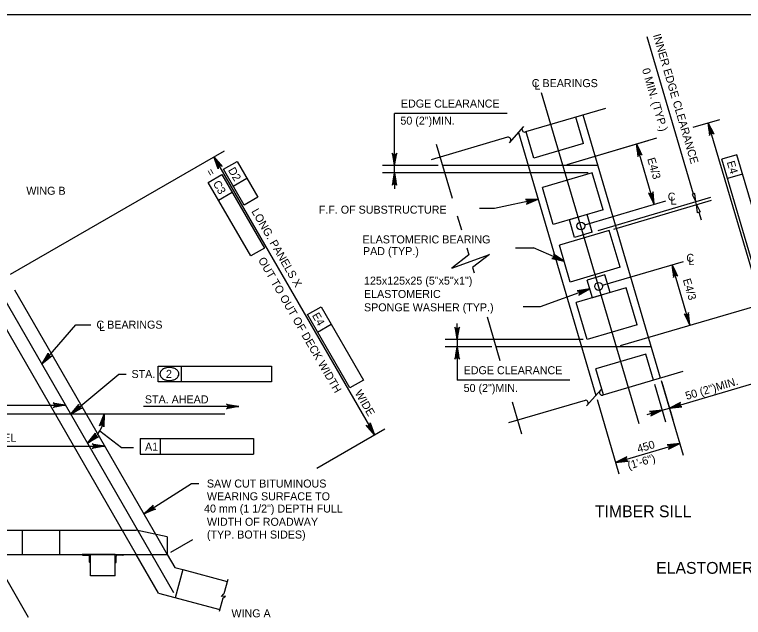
# Model space of a CAD drawing. Extents: x 638268 to 640277, y 295465 to 298435.
# Drawn here: x 639628.9 to 639902.1, y 297006.4 to 297232.5 of the extents above; entities that cross this region are included whole.
import ezdxf

# ---------------------------------------------------------------- set-up
doc = ezdxf.new("R2010")
doc.units = 0
for name, color, linetype in [('2', 7, 'Continuous'), ('3', 7, 'Continuous'), ('4', 7, 'Continuous'), ('7', 7, 'Continuous')]:
    doc.layers.add(name, color=color, linetype=linetype)

msp = doc.modelspace()

# ---------------------------------------------------------------- linework, layer by layer
at = {"layer": '2'}
for p, q in [((639316.46, 297232.46), (640102.46, 297232.46)), ((639614.31, 297134.29), (639674.49, 297030.06)), ((639628.88, 297129.24), (639682.63, 297036.13)), ((639539.28, 297039.18), (639674.46, 297039.18)), ((639631.81, 297030.06), (639631.81, 297039.18)), ((639645.83, 297030.06), (639645.83, 297039.18)), ((639686.14, 297036.58), (639674.46, 297039.18)), ((639686.14, 297036.58), (639686.14, 297030.06)), ((639682.63, 297036.13), (639686.14, 297030.06)), ((639492.13, 297030.06), (639686.14, 297030.06)), ((639492.13, 297030.06), (639686.14, 297030.06)), ((639654.29, 297029.88), (639654.29, 297030.06)), ((639657.38, 297030.06), (639654.29, 297030.06)), ((639654.48, 297029.7), (639656.66, 297029.7)), ((639657.02, 297027.15), (639657.02, 297029.33)), ((639666.62, 297030.06), (639657.38, 297030.06)), ((639657.38, 297026.97), (639657.38, 297030.06)), ((639657.38, 297021.97), (639657.38, 297030.06)), ((639666.62, 297026.97), (639666.62, 297030.06)), ((639666.62, 297030.06), (639669.71, 297030.06)), ((639666.62, 297021.97), (639666.62, 297030.06)), ((639666.98, 297027.15), (639666.98, 297029.33)), ((639669.53, 297029.7), (639667.35, 297029.7)), ((639669.71, 297029.88), (639669.71, 297030.06)), ((639682.91, 297015.46), (639674.49, 297030.06)), ((639686.14, 297030.06), (639688.98, 297025.13)), ((639657.2, 297026.97), (639657.38, 297026.97)), ((639666.8, 297026.97), (639666.62, 297026.97)), ((639688.98, 297025.13), (639691.94, 297024.34)), ((639691.94, 297024.34), (639689.11, 297013.8)), ((639691.94, 297024.34), (639708.62, 297019.87)), ((639666.62, 297021.97), (639657.38, 297021.97)), ((639682.91, 297015.46), (639705.79, 297009.33))]:
    msp.add_line(p, q, dxfattribs=at)
for centre, radius, start, end in [((639654.48, 297029.88), 0.182, 180.0016, 270), ((639656.66, 297029.33), 0.364, 0.0016, 90), ((639667.35, 297029.33), 0.364, 90, 179.9984), ((639669.53, 297029.88), 0.182, 270, 359.9984), ((639657.2, 297027.15), 0.182, 180.0016, 270), ((639666.8, 297027.15), 0.182, 270, 359.9984)]:
    msp.add_arc(centre, radius, start, end, dxfattribs=at)
at = {"layer": '3'}
for p, q in [((639850.43, 297197.27), (639820.41, 297188.43)), ((639871.06, 297096.14), (639842.01, 297194.79)), ((639883.33, 297190.23), (639893.29, 297193.16)), ((639819.72, 297190.5), (639814.31, 297184.36)), ((639908.99, 297123.91), (639888.97, 297191.89)), ((639813.71, 297186.46), (639785.03, 297178.01)), ((639817.76, 297188.28), (639846.82, 297089.63)), ((639786.97, 297183.81), (639792.9, 297163.67)), ((639842.23, 297184.11), (639823.54, 297178.6)), ((639836.01, 297176.29), (639869.64, 297186.19)), ((639847.59, 297175.85), (639789.32, 297175.85)), ((639845.48, 297173.09), (639826.78, 297167.59)), ((639847.72, 297151.52), (639889.91, 297163.95)), ((639853.53, 297152.03), (639890.23, 297162.85)), ((639849.55, 297159.25), (639830.86, 297153.74)), ((639794.88, 297156.95), (639796.43, 297151.7)), ((639843.51, 297157.46), (639836.9, 297155.52)), ((639851.83, 297151.53), (639833.13, 297146.03)), ((639845.46, 297150.86), (639838.85, 297148.91)), ((639798.4, 297145.01), (639799.17, 297142.38)), ((639800.59, 297137.59), (639801.16, 297135.65)), ((639855.9, 297137.69), (639837.21, 297132.18)), ((639850.19, 297134.81), (639843.58, 297132.86)), ((639858.18, 297129.98), (639839.48, 297124.47)), ((639852.13, 297128.2), (639845.53, 297126.25)), ((639856.03, 297108.31), (639913.31, 297125.18)), ((639806.04, 297119.06), (639810.85, 297102.76)), ((639862.25, 297116.13), (639843.56, 297110.62)), ((639867.61, 297107.87), (639809.34, 297107.87)), ((639865.5, 297105.11), (639846.81, 297099.61)), ((639879.48, 297098.62), (639849.47, 297089.78)), ((639848.78, 297091.85), (639843.36, 297085.71)), ((639842.76, 297087.81), (639814.08, 297079.36)), ((639815.4, 297087.29), (639818.93, 297075.3)), ((639708.84, 297020.69), (639707.37, 297015.22)), ((639706.5, 297014.27), (639707.37, 297015.22)), ((639707.96, 297014.36), (639706.5, 297014.27)), ((639706.93, 297013.59), (639707.96, 297014.36)), ((639706.93, 297013.59), (639705.59, 297008.59))]:
    msp.add_line(p, q, dxfattribs=at)
msp.add_lwpolyline([(639890.3, 297189.15), (639889.34, 297188.87), (639888.97, 297191.89)], close=True, dxfattribs=at)
for centre, start, end in [((639820.13, 297189.41), 136.412, 286.412), ((639813.9, 297185.45), 318.5448, 101.0834), ((639849.18, 297090.76), 136.412, 286.412), ((639842.96, 297086.8), 318.5448, 101.0834)]:
    msp.add_arc(centre, 1.02, start, end, dxfattribs=at)
at = {"layer": '4'}
for p, q in [((639883.43, 297165.17), (639866.06, 297224.16)), ((639863.01, 297079.06), (639826.47, 297203.14)), ((639771.31, 297178.85), (639771.31, 297195.39)), ((639813.58, 297195.39), (639771.31, 297195.39)), ((639688.63, 297015.66), (639589.95, 297186.58)), ((639836.01, 297176.29), (639866.38, 297185.23)), ((639868.74, 297161.3), (639862.06, 297183.96)), ((639627.32, 297135.07), (639707.53, 297181.38)), ((639703.63, 297179.13), (639763.8, 297074.9)), ((639899.69, 297179.91), (639894.03, 297178.24)), ((639906.04, 297137.45), (639894.03, 297178.24)), ((639911.7, 297139.12), (639899.69, 297179.91)), ((639707.2, 297174.46), (639712.32, 297177.42)), ((639712.32, 297177.42), (639720.06, 297164)), ((639787.75, 297175.85), (639766.81, 297175.85)), ((639771.31, 297173.09), (639771.31, 297175.85)), ((639714.95, 297161.05), (639707.2, 297174.46)), ((639843.91, 297173.09), (639766.81, 297173.09)), ((639701.52, 297169.49), (639706.64, 297172.44)), ((639706.64, 297172.44), (639722.53, 297144.92)), ((639710.84, 297168.16), (639715.96, 297171.11)), ((639771.31, 297170.09), (639771.31, 297167.09)), ((639901.83, 297172.65), (639896.16, 297170.99)), ((639717.41, 297141.97), (639701.52, 297169.49)), ((639705.35, 297162.87), (639710.46, 297165.82)), ((639720.06, 297164), (639714.95, 297161.05)), ((639842.68, 297153.63), (639873.05, 297162.57)), ((639884.6, 297161.19), (639884.28, 297162.29)), ((639808.76, 297159.78), (639803.23, 297159.78)), ((639885.45, 297158.31), (639886.3, 297155.43)), ((639722.53, 297144.92), (639717.41, 297141.97)), ((639823.57, 297144.87), (639816.72, 297144.87)), ((639849.35, 297130.97), (639879.73, 297139.91)), ((639882.08, 297115.98), (639875.41, 297138.64)), ((639738.67, 297119.98), (639743.78, 297122.93)), ((639743.78, 297122.93), (639759.67, 297095.41)), ((639825.95, 297122.92), (639819.57, 297122.92)), ((639754.56, 297092.46), (639738.67, 297119.98)), ((639639.12, 297101.41), (639651.85, 297116.15)), ((639651.85, 297116.15), (639657.47, 297116.15)), ((639742.49, 297113.35), (639747.61, 297116.31)), ((639794.84, 297113.62), (639794.84, 297116.62)), ((639856.03, 297108.31), (639886.4, 297117.26)), ((639842, 297110.62), (639790.34, 297110.62)), ((639794.84, 297110.62), (639794.84, 297107.87)), ((639807.78, 297107.87), (639790.34, 297107.87)), ((639794.84, 297104.87), (639794.84, 297095.4)), ((639682.7, 297094.75), (639682.7, 297100.65)), ((639682.7, 297100.65), (639725.22, 297100.65)), ((639691.45, 297094.75), (639691.45, 297100.65)), ((639725.22, 297100.65), (639725.22, 297094.75)), ((639649.99, 297082.58), (639667.92, 297097.57)), ((639667.92, 297097.57), (639670.69, 297097.57)), ((639874.38, 297084.88), (639914.06, 297096.57)), ((639725.22, 297094.75), (639682.7, 297094.75)), ((639759.67, 297095.41), (639754.56, 297092.46)), ((639837.1, 297095.4), (639794.84, 297095.4)), ((639868.82, 297093.85), (639872.96, 297079.78)), ((639871.34, 297095.22), (639879.57, 297067.28)), ((639871.51, 297094.65), (639875.65, 297080.57)), ((639847.26, 297088.13), (639855.49, 297060.19)), ((639468.6, 297085.95), (639648.04, 297085.95)), ((639713.02, 297085.52), (639677.21, 297085.52)), ((639871.69, 297084.09), (639865.94, 297082.4)), ((639871.69, 297084.09), (639874.38, 297084.89)), ((639707.69, 297082.58), (639405.47, 297082.58)), ((639742.18, 297062.42), (639767.7, 297077.15)), ((639660.83, 297076.32), (639669.01, 297070.11)), ((639675.94, 297073.48), (639718.45, 297073.48)), ((639675.94, 297073.48), (639675.94, 297067.58)), ((639683.5, 297073.48), (639683.5, 297067.58)), ((639718.45, 297073.48), (639718.45, 297067.58)), ((639471.61, 297070.65), (639662.7, 297070.65)), ((639669.01, 297070.11), (639673.48, 297070.11)), ((639854.22, 297064.5), (639878.3, 297071.6)), ((639598.34, 297068.34), (639634.03, 297006.52)), ((639675.94, 297067.58), (639718.45, 297067.58)), ((639677.37, 297045.24), (639695.2, 297056.69)), ((639695.2, 297056.69), (639697.97, 297056.69)), ((639687.49, 297030.84), (639695.73, 297035.6))]:
    msp.add_line(p, q, dxfattribs=at)
for points in [[(639888.97, 297191.89), (639889.45, 297187.17), (639889.59, 297187.59), (639889.83, 297187.85), (639890.12, 297187.99), (639890.43, 297188.03), (639890.78, 297187.94), (639891.12, 297187.67), (639888.97, 297191.89), (639890.78, 297187.94), (639890.43, 297188.03), (639888.97, 297191.89), (639890.12, 297187.99), (639889.83, 297187.85), (639888.97, 297191.89), (639889.59, 297187.59)], [(639862.06, 297183.96), (639862.54, 297179.25), (639862.68, 297179.66), (639862.92, 297179.92), (639863.21, 297180.06), (639863.52, 297180.1), (639863.88, 297180.01), (639864.21, 297179.74), (639862.06, 297183.96), (639863.88, 297180.01), (639863.52, 297180.1), (639862.06, 297183.96), (639863.21, 297180.06), (639862.92, 297179.92), (639862.06, 297183.96), (639862.68, 297179.66)], [(639703.63, 297179.13), (639706.72, 297175.53), (639706.32, 297175.71), (639705.96, 297175.72), (639705.66, 297175.61), (639705.42, 297175.41), (639705.24, 297175.09), (639705.2, 297174.65), (639703.63, 297179.13), (639705.24, 297175.09), (639705.42, 297175.41), (639703.63, 297179.13), (639705.66, 297175.61), (639705.96, 297175.72), (639703.63, 297179.13), (639706.32, 297175.71)], [(639771.31, 297175.85), (639772.19, 297180.51), (639771.94, 297180.15), (639771.63, 297179.96), (639771.31, 297179.91), (639771, 297179.96), (639770.69, 297180.15), (639770.44, 297180.51), (639771.31, 297175.85), (639770.69, 297180.15), (639771, 297179.96), (639771.31, 297175.85), (639771.31, 297179.91), (639771.63, 297179.96), (639771.31, 297175.85), (639771.94, 297180.15)], [(639771.31, 297173.09), (639770.44, 297168.43), (639770.69, 297168.79), (639771, 297168.97), (639771.31, 297169.03), (639771.63, 297168.97), (639771.94, 297168.79), (639772.19, 297168.43), (639771.31, 297173.09), (639771.94, 297168.79), (639771.63, 297168.97), (639771.31, 297173.09), (639771.31, 297169.03), (639771, 297168.97), (639771.31, 297173.09), (639770.69, 297168.79)], [(639868.74, 297161.3), (639868.26, 297166.02), (639868.12, 297165.61), (639867.87, 297165.34), (639867.59, 297165.2), (639867.27, 297165.16), (639866.92, 297165.25), (639866.58, 297165.53), (639868.74, 297161.3), (639866.92, 297165.25), (639867.27, 297165.16), (639868.74, 297161.3), (639867.59, 297165.2), (639867.87, 297165.34), (639868.74, 297161.3), (639868.12, 297165.61)], [(639825.14, 297163.23), (639808.76, 297159.78)], [(639825.14, 297163.23), (639820.4, 297163.12), (639820.8, 297162.96), (639821.05, 297162.69), (639821.17, 297162.39), (639821.18, 297162.08), (639821.06, 297161.73), (639820.76, 297161.42), (639825.14, 297163.23), (639821.06, 297161.73), (639821.18, 297162.08), (639825.14, 297163.23), (639821.17, 297162.39), (639821.05, 297162.69), (639825.14, 297163.23), (639820.8, 297162.96)], [(639834.91, 297139.97), (639823.41, 297144.94)], [(639799.17, 297142.38), (639792.84, 297137.35), (639806.97, 297142.45), (639800.58, 297137.59)], [(639834.91, 297139.97), (639830.98, 297142.62), (639831.21, 297142.25), (639831.26, 297141.89), (639831.19, 297141.58), (639831.01, 297141.32), (639830.72, 297141.11), (639830.29, 297141.02), (639834.91, 297139.97), (639830.72, 297141.11), (639831.01, 297141.32), (639834.91, 297139.97), (639831.19, 297141.58), (639831.26, 297141.89), (639834.91, 297139.97), (639831.21, 297142.25)], [(639875.41, 297138.64), (639875.89, 297133.93), (639876.03, 297134.34), (639876.27, 297134.61), (639876.56, 297134.75), (639876.87, 297134.78), (639877.22, 297134.69), (639877.56, 297134.42), (639875.41, 297138.64), (639877.22, 297134.69), (639876.87, 297134.78), (639875.41, 297138.64), (639876.56, 297134.75), (639876.27, 297134.61), (639875.41, 297138.64), (639876.03, 297134.34)], [(639844.54, 297129.61), (639825.94, 297122.92)], [(639844.54, 297129.61), (639839.85, 297128.85), (639840.28, 297128.74), (639840.56, 297128.51), (639840.71, 297128.23), (639840.77, 297127.92), (639840.7, 297127.56), (639840.45, 297127.21), (639844.54, 297129.61), (639840.7, 297127.56), (639840.77, 297127.92), (639844.54, 297129.61), (639840.71, 297128.23), (639840.56, 297128.51), (639844.54, 297129.61), (639840.28, 297128.74)], [(639882.08, 297115.98), (639881.6, 297120.7), (639881.47, 297120.29), (639881.22, 297120.02), (639880.94, 297119.88), (639880.62, 297119.85), (639880.27, 297119.93), (639879.93, 297120.21), (639882.08, 297115.98), (639880.27, 297119.93), (639880.62, 297119.85), (639882.08, 297115.98), (639880.94, 297119.88), (639881.22, 297120.02), (639882.08, 297115.98), (639881.47, 297120.29)], [(639794.84, 297110.62), (639795.71, 297115.28), (639795.46, 297114.93), (639795.15, 297114.74), (639794.84, 297114.69), (639794.52, 297114.74), (639794.21, 297114.93), (639793.96, 297115.28), (639794.84, 297110.62), (639794.21, 297114.93), (639794.52, 297114.74), (639794.84, 297110.62), (639794.84, 297114.69), (639795.15, 297114.74), (639794.84, 297110.62), (639795.46, 297114.93)], [(639794.84, 297107.87), (639793.96, 297103.21), (639794.21, 297103.57), (639794.52, 297103.75), (639794.84, 297103.81), (639795.15, 297103.75), (639795.46, 297103.57), (639795.71, 297103.21), (639794.84, 297107.87), (639795.46, 297103.57), (639795.15, 297103.75), (639794.84, 297107.87), (639794.84, 297103.81), (639794.52, 297103.75), (639794.84, 297107.87), (639794.21, 297103.57)], [(639639.12, 297101.41), (639641.5, 297105.51), (639641.46, 297105.07), (639641.57, 297104.73), (639641.77, 297104.48), (639642.05, 297104.32), (639642.4, 297104.26), (639642.83, 297104.36), (639639.12, 297101.41), (639642.4, 297104.26), (639642.05, 297104.32), (639639.12, 297101.41), (639641.77, 297104.48), (639641.57, 297104.73), (639639.12, 297101.41), (639641.46, 297105.07)], [(639648.04, 297085.95), (639643.38, 297085.08), (639643.74, 297085.33), (639643.93, 297085.64), (639643.98, 297085.95), (639643.93, 297086.27), (639643.74, 297086.58), (639643.38, 297086.83), (639648.04, 297085.95), (639643.74, 297086.58), (639643.93, 297086.27), (639648.04, 297085.95), (639643.98, 297085.95), (639643.93, 297085.64), (639648.04, 297085.95), (639643.74, 297085.33)], [(639649.99, 297082.58), (639653, 297086.24), (639652.89, 297085.82), (639652.95, 297085.46), (639653.11, 297085.19), (639653.35, 297084.98), (639653.69, 297084.86), (639654.12, 297084.9), (639649.99, 297082.58), (639653.69, 297084.86), (639653.35, 297084.98), (639649.99, 297082.58), (639653.11, 297085.19), (639652.95, 297085.46), (639649.99, 297082.58), (639652.89, 297085.82)], [(639713.02, 297085.52), (639708.36, 297084.65), (639708.72, 297084.89), (639708.91, 297085.21), (639708.96, 297085.52), (639708.91, 297085.83), (639708.72, 297086.14), (639708.36, 297086.39), (639713.02, 297085.52), (639708.72, 297086.14), (639708.91, 297085.83), (639713.02, 297085.52), (639708.96, 297085.52), (639708.91, 297085.21), (639713.02, 297085.52), (639708.72, 297084.89)], [(639874.38, 297084.88), (639879.1, 297085.36), (639878.68, 297085.5), (639878.42, 297085.75), (639878.28, 297086.03), (639878.24, 297086.35), (639878.33, 297086.7), (639878.6, 297087.04), (639874.38, 297084.88), (639878.33, 297086.7), (639878.24, 297086.35), (639874.38, 297084.88), (639878.28, 297086.03), (639878.42, 297085.75), (639874.38, 297084.88), (639878.68, 297085.5)], [(639871.69, 297084.09), (639866.98, 297083.61), (639867.39, 297083.48), (639867.65, 297083.23), (639867.79, 297082.95), (639867.83, 297082.63), (639867.74, 297082.28), (639867.47, 297081.94), (639871.69, 297084.09), (639867.74, 297082.28), (639867.83, 297082.63), (639871.69, 297084.09), (639867.79, 297082.95), (639867.65, 297083.23), (639871.69, 297084.09), (639867.39, 297083.48)], [(639662.51, 297082.58), (639662.4, 297077.84), (639662.23, 297078.24), (639661.96, 297078.49), (639661.67, 297078.61), (639661.35, 297078.62), (639661.01, 297078.5), (639660.69, 297078.2), (639662.51, 297082.58), (639661.01, 297078.5), (639661.35, 297078.62), (639662.51, 297082.58), (639661.67, 297078.61), (639661.96, 297078.49), (639662.51, 297082.58), (639662.23, 297078.24)], [(639763.8, 297074.9), (639760.72, 297078.5), (639761.11, 297078.31), (639761.48, 297078.31), (639761.77, 297078.42), (639762.02, 297078.62), (639762.2, 297078.94), (639762.23, 297079.37), (639763.8, 297074.9), (639762.2, 297078.94), (639762.02, 297078.62), (639763.8, 297074.9), (639761.77, 297078.42), (639761.48, 297078.31), (639763.8, 297074.9), (639761.11, 297078.31)], [(639656.25, 297071.74), (639659.2, 297075.45), (639659.1, 297075.03), (639659.16, 297074.67), (639659.32, 297074.4), (639659.57, 297074.19), (639659.91, 297074.08), (639660.35, 297074.13), (639656.25, 297071.74), (639659.91, 297074.08), (639659.57, 297074.19), (639656.25, 297071.74), (639659.32, 297074.4), (639659.16, 297074.67), (639656.25, 297071.74), (639659.1, 297075.03)], [(639662.7, 297070.65), (639658.04, 297069.78), (639658.4, 297070.03), (639658.59, 297070.34), (639658.64, 297070.65), (639658.59, 297070.96), (639658.4, 297071.28), (639658.04, 297071.52), (639662.7, 297070.65), (639658.4, 297071.28), (639658.59, 297070.96), (639662.7, 297070.65), (639658.64, 297070.65), (639658.59, 297070.34), (639662.7, 297070.65), (639658.4, 297070.03)], [(639878.3, 297071.6), (639873.58, 297071.12), (639873.99, 297070.98), (639874.26, 297070.73), (639874.4, 297070.45), (639874.44, 297070.13), (639874.35, 297069.78), (639874.07, 297069.44), (639878.3, 297071.6), (639874.35, 297069.78), (639874.44, 297070.13), (639878.3, 297071.6), (639874.4, 297070.45), (639874.26, 297070.73), (639878.3, 297071.6), (639873.99, 297070.98)], [(639854.22, 297064.5), (639858.94, 297064.98), (639858.52, 297065.12), (639858.26, 297065.37), (639858.12, 297065.65), (639858.08, 297065.97), (639858.17, 297066.32), (639858.44, 297066.66), (639854.22, 297064.5), (639858.17, 297066.32), (639858.08, 297065.97), (639854.22, 297064.5), (639858.12, 297065.65), (639858.26, 297065.37), (639854.22, 297064.5), (639858.52, 297065.12)], [(639677.37, 297045.24), (639680.82, 297048.49), (639680.66, 297048.09), (639680.67, 297047.73), (639680.79, 297047.43), (639681.01, 297047.2), (639681.33, 297047.04), (639681.77, 297047.02), (639677.37, 297045.24), (639681.33, 297047.04), (639681.01, 297047.2), (639677.37, 297045.24), (639680.79, 297047.43), (639680.67, 297047.73), (639677.37, 297045.24), (639680.66, 297048.09)]]:
    msp.add_lwpolyline(points, dxfattribs=at)
for points in [[(639863.39, 297181.23), (639862.43, 297180.94), (639862.06, 297183.96)], [(639705.56, 297176.78), (639704.7, 297176.28), (639703.63, 297179.13)], [(639771.81, 297178.85), (639770.81, 297178.85), (639771.31, 297175.85)], [(639771.81, 297170.09), (639770.81, 297170.09), (639771.31, 297173.09)], [(639883.91, 297165.31), (639882.95, 297165.03), (639884.28, 297162.29)], [(639825.14, 297163.23), (639822.26, 297162.37), (639822.15, 297162.86)], [(639868.37, 297164.32), (639867.41, 297164.04), (639868.74, 297161.3)], [(639885.93, 297158.45), (639884.97, 297158.17), (639884.6, 297161.19)], [(639834.91, 297139.97), (639832.06, 297140.93), (639832.26, 297141.39)], [(639876.74, 297135.91), (639875.78, 297135.62), (639875.41, 297138.64)], [(639844.54, 297129.61), (639841.8, 297128.36), (639841.63, 297128.83)], [(639881.71, 297119), (639880.76, 297118.72), (639882.08, 297115.98)], [(639795.34, 297113.62), (639794.34, 297113.62), (639794.84, 297110.62)], [(639795.34, 297104.87), (639794.34, 297104.87), (639794.84, 297107.87)], [(639877.12, 297086.21), (639877.4, 297085.25), (639874.38, 297084.89)], [(639651.82, 297084.71), (639652.41, 297084), (639649.99, 297082.58)], [(639868.67, 297083.73), (639868.95, 297082.77), (639871.69, 297084.09)], [(639762.74, 297077.75), (639761.87, 297077.25), (639763.8, 297074.9)], [(639875.28, 297071.23), (639875.56, 297070.27), (639878.3, 297071.6)], [(639856.96, 297065.83), (639857.24, 297064.87), (639854.22, 297064.5)], [(639680.32, 297046.58), (639679.82, 297047.36), (639677.74, 297045.47)]]:
    msp.add_lwpolyline(points, close=True, dxfattribs=at)
for centre, radius, start, end in [((639685.95, 297097.13), 2.75, 124.109, 148.5507), ((639686.55, 297096.24), 3.82, 105.6708, 124.109), ((639686.94, 297094.84), 5.27, 90, 105.6708), ((639686.94, 297094.84), 5.27, 74.3292, 90), ((639687.33, 297096.24), 3.82, 55.891, 74.3292), ((639687.93, 297097.13), 2.75, 31.4493, 55.891), ((639685.03, 297097.69), 1.68, 148.5507, 180), ((639685.03, 297097.69), 1.68, 180, 211.4493), ((639685.95, 297098.25), 2.75, 211.4493, 235.891), ((639687.93, 297098.25), 2.75, 304.109, 328.5507), ((639688.84, 297097.69), 1.68, 0, 31.4493), ((639688.84, 297097.69), 1.68, 328.5507, 0), ((639686.55, 297099.13), 3.82, 235.891, 254.3292), ((639686.94, 297100.53), 5.27, 254.3292, 270), ((639686.94, 297100.53), 5.27, 270, 285.6708), ((639687.33, 297099.13), 3.82, 285.6708, 304.109), ((639649.99, 297082.58), 12.52, 299.9992, 0.0004)]:
    msp.add_arc(centre, radius, start, end, dxfattribs=at)
at = {"layer": '7'}
for p, q in [((639842.23, 297184.11), (639839.32, 297194)), ((639823.54, 297178.6), (639820.63, 297188.49)), ((639849.55, 297159.25), (639845.48, 297173.09)), ((639830.86, 297153.74), (639826.78, 297167.59)), ((639845.46, 297150.86), (639843.51, 297157.46)), ((639838.85, 297148.91), (639836.9, 297155.52)), ((639855.9, 297137.69), (639851.83, 297151.53)), ((639837.21, 297132.18), (639833.13, 297146.03)), ((639852.13, 297128.2), (639850.19, 297134.81)), ((639845.53, 297126.25), (639843.58, 297132.86)), ((639862.25, 297116.13), (639858.18, 297129.98)), ((639843.56, 297110.62), (639839.48, 297124.47)), ((639868.38, 297095.35), (639865.5, 297105.11)), ((639849.68, 297089.85), (639846.81, 297099.61))]:
    msp.add_line(p, q, dxfattribs=at)
for centre in [(639841.18, 297153.19), (639847.86, 297130.53)]:
    msp.add_circle(centre, 1.48, dxfattribs=at)

# ---------------------------------------------------------------- texts
at = {"layer": '3'}
for s, p in [('TIMBER SILL', (639846.46, 297043.99)), ('ELASTOMERIC BEARING PAD ARRANGEMENTS', (639869.42, 297022.77))]:
    msp.add_text(s, height=4.4292, dxfattribs=at).set_placement(p)
at = {"layer": '4'}
for s, rotation, p in [('INNER EDGE CLEARANCE', 286.412, (639868.21, 297224.73)), ('0 MIN. (TYP.)', 286.412, (639864.06, 297211.89)), ('E4/3', 286.412, (639866.04, 297178.35)), ('E4', 286.4738, (639895.87, 297177.12)), ('=', 300, (639700.55, 297173.65)), ('D2', 300, (639708.82, 297174.14)), ('C3', 300, (639703.14, 297169.17)), ('LONG. PANELS X', 300, (639717.58, 297158.67)), ('OUT TO OUT OF DECK WIDTH', 300, (639720.08, 297140.43)), ('E4/3', 286.412, (639879.39, 297133.03)), ('E4', 300, (639740.29, 297119.65)), ('50 (2")MIN.', 16.4163, (639880.88, 297087.95)), ('WIDE', 300, (639756.32, 297090.62)), ('A1', 359.9382, (639677.8, 297068.93)), ('450', 16.4163, (639862.78, 297068.11)), ('(1\'-6")', 16.4163, (639859.19, 297061.84))]:
    msp.add_text(s, height=3, rotation=rotation, dxfattribs=at).set_placement(p)
for s, p in [('C BEARINGS', (639822.8, 297205.25)), ('L', (639823.82, 297204.34)), ('EDGE CLEARANCE', (639773.73, 297197.59)), ('50 (2")MIN.', (639773.54, 297191.18)), ('WING B', (639633.29, 297164.9)), ('C', (639873.77, 297162.69)), ('L', (639874.83, 297161.17)), ('F.F. OF SUBSTRUCTURE', (639742.94, 297157.81)), ('ELASTOMERIC BEARING', (639759.36, 297146.65)), ('PAD (TYP.)', (639759.51, 297142.27)), ('C', (639880.75, 297139.73)), ('L', (639881.5, 297138.51)), ('125x125x25 (5"x5"x1")', (639759.89, 297131.19)), ('ELASTOMERIC', (639759.89, 297126.19)), ('SPONGE WASHER (TYP.)', (639759.89, 297121.19)), ('C BEARINGS', (639659.6, 297114.69)), ('L', (639660.55, 297113.83)), ('STA.', (639672.74, 297096.18)), ('2', (639685.64, 297096.23)), ('EDGE CLEARANCE', (639797.25, 297097.6)), ('50 (2")MIN.', (639797.25, 297090.95)), ('STA. AHEAD', (639677.75, 297086.67)), ('OUT TO OUT LONGITUDINAL PANEL', (639559.76, 297072.27)), ('SAW CUT BITUMINOUS', (639701, 297055.11)), ('WEARING SURFACE TO', (639701, 297050.33)), ('40 mm (1 1/2") DEPTH FULL', (639699.93, 297045.73)), ('WIDTH OF ROADWAY', (639701, 297040.77)), ('(TYP. BOTH SIDES)', (639701, 297035.99)), ('WING A', (639710.19, 297006.45))]:
    msp.add_text(s, height=3, dxfattribs=at).set_placement(p)

doc.saveas('drawing.dxf')
